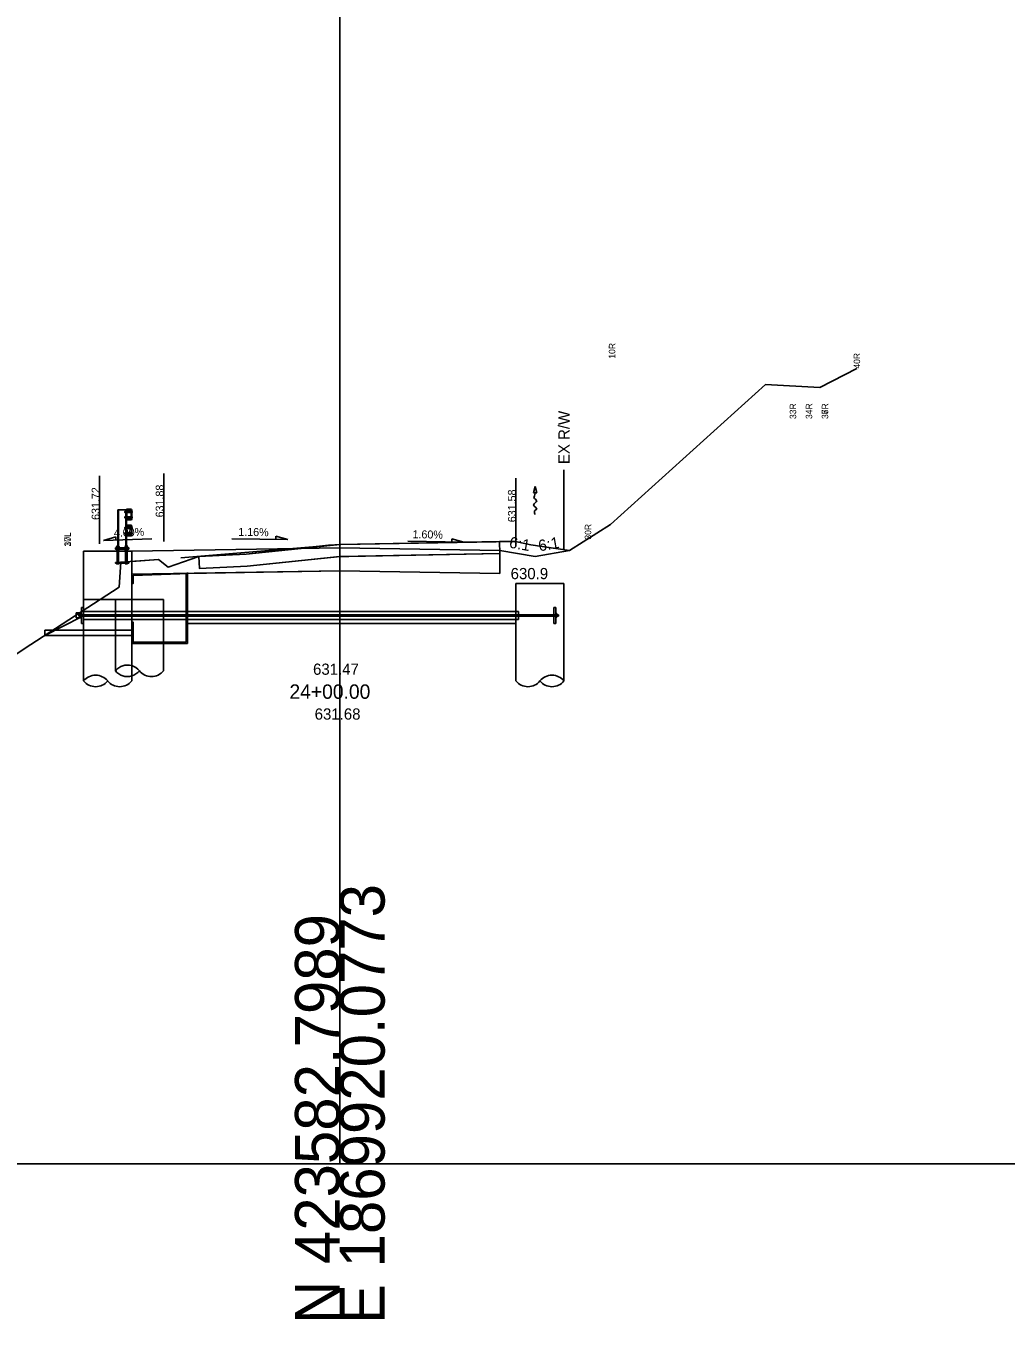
# Model space of a CAD drawing. Extents: x 1866342 to 1870084, y 421982 to 426629.
# Drawn here: x 1866448.5 to 1866509.7, y 424480.9 to 424561.7 of the extents above; entities that cross this region are included whole.
import ezdxf

# ---------------------------------------------------------------- set-up
doc = ezdxf.new("R2010")
doc.units = 0
for name, color, linetype in [('BR_P_Det_Object', 7, 'Continuous'), ('BR_P_Drain_Object', 7, 'Continuous'), ('BR_P_Gen_Hatch', 7, 'Continuous'), ('BR_P_Gen_Porous_Backfill', 7, 'Continuous'), ('BR_P_Sub_Deep_Hidden', 7, 'Continuous'), ('BR_P_Sub_Deep_Object', 7, 'Continuous'), ('BR_P_Sub_Object', 7, 'Continuous'), ('DR_P_Flow_Arrow', 7, 'Continuous'), ('GK_Cells', 7, 'Continuous'), ('RW_X_Fee_RW', 7, 'Continuous'), ('ST_Details', 7, 'Continuous'), ('XS_P_Annotation', 7, 'Continuous'), ('XS_P_Earthwork_Shapes', 7, 'Continuous'), ('XS_P_Finished_Grade', 7, 'Continuous'), ('XS_P_Pavt_Surface', 7, 'Continuous'), ('XS_P_Subgrade', 7, 'Continuous'), ('XS_P_Text_Info', 7, 'Continuous'), ('XS_P_Text_MarkedPoint', 7, 'Continuous'), ('XS_X_Ground_Line', 7, 'Continuous')]:
    doc.layers.add(name, color=color, linetype=linetype)

msp = doc.modelspace()

# ---------------------------------------------------------------- linework, layer by layer
at = {"layer": 'BR_P_Det_Object'}
for p, q in [((1866451.66, 424524.746), (1866451.66, 424525.044)), ((1866451.66, 424525.044), (1866451.994, 424525.044)), ((1866451.994, 424524.746), (1866451.66, 424524.746)), ((1866451.827, 424524.938), (1866481.785, 424524.938)), ((1866451.827, 424524.855), (1866451.827, 424524.938)), ((1866451.827, 424524.855), (1866481.785, 424524.855)), ((1866451.994, 424524.991), (1866451.93, 424524.991)), ((1866451.93, 424524.802), (1866451.93, 424524.991)), ((1866451.994, 424524.802), (1866451.93, 424524.802)), ((1866451.994, 424524.396), (1866451.994, 424525.396)), ((1866451.994, 424525.396), (1866452.119, 424525.396)), ((1866452.119, 424525.396), (1866452.119, 424524.396)), ((1866452.119, 424525.146), (1866455.119, 424525.146)), ((1866481.494, 424525.396), (1866481.494, 424524.396)), ((1866481.619, 424525.396), (1866481.494, 424525.396)), ((1866481.619, 424524.396), (1866481.619, 424525.396)), ((1866481.619, 424525.011), (1866481.682, 424525.011)), ((1866481.619, 424524.781), (1866481.682, 424524.781)), ((1866481.682, 424524.781), (1866481.682, 424525.011)), ((1866481.785, 424524.855), (1866481.785, 424524.938)), ((1866452.119, 424524.396), (1866451.994, 424524.396)), ((1866452.119, 424524.646), (1866455.119, 424524.646)), ((1866481.619, 424524.396), (1866481.494, 424524.396))]:
    msp.add_line(p, q, dxfattribs=at)
at = {"layer": 'BR_P_Drain_Object'}
for p, q in [((1866455.119, 424525.146), (1866479.285, 424525.146)), ((1866479.285, 424525.146), (1866479.285, 424524.646)), ((1866449.695, 424523.98), (1866455.119, 424523.98)), ((1866449.695, 424523.646), (1866449.695, 424523.98)), ((1866455.119, 424524.646), (1866479.285, 424524.646)), ((1866449.695, 424523.646), (1866455.119, 424523.646))]:
    msp.add_line(p, q, dxfattribs=at)
at = {"layer": 'BR_P_Gen_Hatch'}
msp.add_lwpolyline([(1866455.119, 424526.879), (1866455.202, 424526.879), (1866455.202, 424527.379), (1866458.519, 424527.502), (1866458.519, 424523.23), (1866455.202, 424523.23), (1866455.202, 424524.48), (1866455.119, 424524.48)], close=True, dxfattribs=at)
at = {"layer": 'BR_P_Gen_Porous_Backfill'}
for p, q in [((1866455.202, 424527.379), (1866458.119, 424527.496)), ((1866455.202, 424526.879), (1866455.202, 424527.379)), ((1866458.519, 424527.502), (1866458.119, 424527.496)), ((1866458.519, 424523.23), (1866458.519, 424527.502)), ((1866455.202, 424526.879), (1866455.119, 424526.879)), ((1866455.202, 424524.48), (1866455.119, 424524.48)), ((1866455.202, 424523.23), (1866455.202, 424524.48)), ((1866455.202, 424523.23), (1866458.519, 424523.23))]:
    msp.add_line(p, q, dxfattribs=at)
at = {"layer": 'BR_P_Sub_Deep_Hidden'}
msp.add_line((1866457.103, 424525.896), (1866455.119, 424525.896), dxfattribs=at)
for points in [[(1866454.103, 424521.433), (1866454.103, 424525.896)], [(1866457.103, 424523.146), (1866457.103, 424525.896)]]:
    msp.add_lwpolyline(points, dxfattribs=at)
for centre, major_axis, start_param, end_param in [((1866454.853, 424520.83), (0.908, 0.32), 0.952163, 2.125879), ((1866454.853, 424522.036), (0.908, -0.32), 4.157306, 5.331022)]:
    msp.add_ellipse(centre, major_axis=major_axis, ratio=0.999997, start_param=start_param, end_param=end_param, dxfattribs=at)
at = {"layer": 'BR_P_Sub_Deep_Object'}
msp.add_line((1866479.119, 424526.896), (1866482.119, 424526.896), dxfattribs=at)
for points in [[(1866479.119, 424520.8), (1866479.119, 424526.896)], [(1866482.119, 424520.8), (1866482.119, 424526.896)], [(1866452.119, 424520.8), (1866452.119, 424525.896)], [(1866455.119, 424520.8), (1866455.119, 424525.896)], [(1866457.103, 424521.433), (1866457.103, 424523.146)]]:
    msp.add_lwpolyline(points, dxfattribs=at)
for centre, major_axis, start_param, end_param in [((1866454.853, 424520.83), (0.908, 0.32), 0.338571, 0.952163), ((1866452.869, 424520.197), (0.908, 0.32), 0.338571, 2.125879), ((1866452.869, 424521.403), (0.908, -0.32), 4.157306, 5.944615), ((1866454.369, 424521.403), (0.908, 0.32), 3.480163, 5.267472), ((1866454.853, 424522.036), (0.908, -0.32), 5.331022, 5.944615), ((1866456.353, 424522.036), (0.908, 0.32), 3.480163, 5.267472), ((1866479.869, 424521.403), (-0.908, 0.32), 1.015713, 2.803022), ((1866481.369, 424520.197), (-0.908, 0.32), 4.157306, 5.944615), ((1866481.369, 424521.403), (-0.908, -0.32), 0.33857, 2.125879)]:
    msp.add_ellipse(centre, major_axis=major_axis, ratio=0.999997, start_param=start_param, end_param=end_param, dxfattribs=at)
at = {"layer": 'BR_P_Sub_Object'}
for p, q in [((1866455.119, 424528.896), (1866452.119, 424528.896)), ((1866452.119, 424528.896), (1866452.119, 424525.896)), ((1866455.119, 424525.896), (1866455.119, 424528.896))]:
    msp.add_line(p, q, dxfattribs=at)
msp.add_lwpolyline([(1866455.119, 424525.896), (1866452.119, 424525.896)], dxfattribs=at)
at = {"layer": 'DR_P_Flow_Arrow'}
for p, q in [((1866480.205, 424532.54), (1866480.312, 424532.94)), ((1866480.312, 424532.94), (1866480.419, 424532.54)), ((1866480.419, 424532.54), (1866480.205, 424532.54))]:
    msp.add_line(p, q, dxfattribs=at)
msp.add_spline([(1866480.311, 424532.54), (1866480.311, 424532.525), (1866480.273, 424532.36), (1866480.237, 424532.256), (1866480.421, 424532.044), (1866480.215, 424531.801), (1866480.421, 424531.521), (1866480.309, 424531.465), (1866480.312, 424531.19)], degree=3, dxfattribs=at)
at = {"layer": 'GK_Cells'}
for p, q in [((1866468.119, 424490.634), (1866468.119, 424639.643)), ((1866368.119, 424490.634), (1866468.119, 424490.634)), ((1866468.119, 424490.634), (1866568.119, 424490.634))]:
    msp.add_line(p, q, dxfattribs=at)
at = {"layer": 'RW_X_Fee_RW'}
msp.add_line((1866482.119, 424528.993), (1866482.119, 424533.993), dxfattribs=at)
at = {"layer": 'ST_Details'}
for p, q in [((1866454.254, 424531.48), (1866454.254, 424529.261)), ((1866454.785, 424531.48), (1866454.254, 424531.48)), ((1866454.292, 424531.48), (1866454.292, 424529.255)), ((1866454.701, 424531.381), (1866454.685, 424531.381)), ((1866454.685, 424531.381), (1866454.685, 424531.329)), ((1866454.701, 424531.329), (1866454.685, 424531.329)), ((1866454.701, 424531.388), (1866454.701, 424531.321)), ((1866454.71, 424531.333), (1866454.747, 424531.333)), ((1866454.747, 424531.399), (1866454.711, 424531.399)), ((1866454.711, 424531.377), (1866454.747, 424531.377)), ((1866454.711, 424531.31), (1866454.747, 424531.31)), ((1866454.747, 424531.48), (1866454.747, 424529.255)), ((1866454.747, 424531.31), (1866454.747, 424531.399)), ((1866454.785, 424531.48), (1866454.785, 424529.261)), ((1866454.785, 424531.469), (1866454.785, 424530.907)), ((1866454.811, 424531.469), (1866454.811, 424530.907)), ((1866454.811, 424531.381), (1866455.093, 424531.381)), ((1866454.811, 424531.329), (1866455.093, 424531.329)), ((1866455.067, 424531.521), (1866454.837, 424531.521)), ((1866455.067, 424531.495), (1866454.837, 424531.495)), ((1866455.093, 424530.907), (1866455.093, 424531.469)), ((1866455.119, 424530.907), (1866455.119, 424531.469)), ((1866454.701, 424531.047), (1866454.685, 424531.047)), ((1866454.685, 424531.047), (1866454.685, 424530.995)), ((1866454.701, 424530.995), (1866454.685, 424530.995)), ((1866454.701, 424531.055), (1866454.701, 424530.988)), ((1866454.71, 424530.999), (1866454.747, 424530.999)), ((1866454.747, 424531.066), (1866454.711, 424531.066)), ((1866454.711, 424531.043), (1866454.747, 424531.043)), ((1866454.711, 424530.977), (1866454.747, 424530.977)), ((1866454.747, 424530.399), (1866454.711, 424530.399)), ((1866454.747, 424530.977), (1866454.747, 424531.066)), ((1866454.747, 424530.31), (1866454.747, 424530.399)), ((1866454.785, 424530.49), (1866454.785, 424529.886)), ((1866454.811, 424531.047), (1866455.093, 424531.047)), ((1866454.811, 424530.995), (1866455.093, 424530.995)), ((1866454.811, 424530.469), (1866454.811, 424529.907)), ((1866455.087, 424530.521), (1866454.817, 424530.521)), ((1866454.837, 424530.881), (1866455.067, 424530.881)), ((1866454.837, 424530.855), (1866455.067, 424530.855)), ((1866455.067, 424530.495), (1866454.837, 424530.495)), ((1866455.093, 424529.907), (1866455.093, 424530.469)), ((1866455.119, 424529.886), (1866455.119, 424530.49)), ((1866454.701, 424530.381), (1866454.685, 424530.381)), ((1866454.685, 424530.381), (1866454.685, 424530.329)), ((1866454.701, 424530.329), (1866454.685, 424530.329)), ((1866454.701, 424530.047), (1866454.685, 424530.047)), ((1866454.685, 424530.047), (1866454.685, 424529.995)), ((1866454.701, 424529.995), (1866454.685, 424529.995)), ((1866454.701, 424530.388), (1866454.701, 424530.321)), ((1866454.701, 424530.055), (1866454.701, 424529.988)), ((1866454.71, 424530.333), (1866454.747, 424530.333)), ((1866454.71, 424529.999), (1866454.747, 424529.999)), ((1866454.711, 424530.377), (1866454.747, 424530.377)), ((1866454.711, 424530.31), (1866454.747, 424530.31)), ((1866454.747, 424530.066), (1866454.711, 424530.066)), ((1866454.711, 424530.043), (1866454.747, 424530.043)), ((1866454.711, 424529.977), (1866454.747, 424529.977)), ((1866454.747, 424529.977), (1866454.747, 424530.066)), ((1866454.811, 424530.381), (1866455.093, 424530.381)), ((1866454.811, 424530.329), (1866455.093, 424530.329)), ((1866454.811, 424530.047), (1866455.093, 424530.047)), ((1866454.811, 424529.995), (1866455.093, 424529.995)), ((1866454.817, 424529.855), (1866455.087, 424529.855)), ((1866454.837, 424529.881), (1866455.067, 424529.881)), ((1866454.171, 424529.13), (1866454.337, 424529.13)), ((1866454.171, 424529.115), (1866454.171, 424529.13)), ((1866454.337, 424529.115), (1866454.171, 424529.115)), ((1866454.171, 424529.032), (1866454.337, 424529.032)), ((1866454.171, 424529.017), (1866454.171, 424529.032)), ((1866454.337, 424529.017), (1866454.171, 424529.017)), ((1866454.176, 424529.196), (1866454.176, 424529.13)), ((1866454.332, 424529.13), (1866454.176, 424529.13)), ((1866454.176, 424528.987), (1866454.176, 424529.017)), ((1866454.195, 424529.212), (1866454.312, 424529.212)), ((1866454.195, 424528.972), (1866454.312, 424528.972)), ((1866454.212, 424529.251), (1866454.223, 424529.261)), ((1866454.212, 424529.251), (1866454.296, 424529.251)), ((1866454.212, 424529.251), (1866454.212, 424529.212)), ((1866454.212, 424529.24), (1866454.296, 424529.24)), ((1866454.212, 424529.23), (1866454.296, 424529.23)), ((1866454.212, 424529.22), (1866454.296, 424529.22)), ((1866454.212, 424529.115), (1866454.212, 424529.032)), ((1866454.212, 424528.907), (1866454.212, 424528.972)), ((1866454.212, 424528.907), (1866454.212, 424528.188)), ((1866454.215, 424529.196), (1866454.215, 424529.13)), ((1866454.215, 424528.987), (1866454.215, 424529.017)), ((1866454.285, 424529.261), (1866454.223, 424529.261)), ((1866454.285, 424529.261), (1866454.296, 424529.251)), ((1866454.293, 424529.196), (1866454.293, 424529.13)), ((1866454.293, 424528.987), (1866454.293, 424529.017)), ((1866454.296, 424529.212), (1866454.296, 424529.251)), ((1866454.296, 424529.032), (1866454.296, 424529.115)), ((1866454.296, 424528.907), (1866454.296, 424528.972)), ((1866454.296, 424528.188), (1866454.296, 424528.907)), ((1866454.332, 424529.196), (1866454.332, 424529.13)), ((1866454.332, 424528.987), (1866454.332, 424529.017)), ((1866454.337, 424529.13), (1866454.337, 424529.115)), ((1866454.337, 424529.032), (1866454.337, 424529.017)), ((1866454.868, 424529.13), (1866454.702, 424529.13)), ((1866454.702, 424529.13), (1866454.702, 424529.115)), ((1866454.702, 424529.115), (1866454.868, 424529.115)), ((1866454.702, 424529.032), (1866454.868, 424529.032)), ((1866454.702, 424529.017), (1866454.702, 424529.032)), ((1866454.868, 424529.017), (1866454.702, 424529.017)), ((1866454.707, 424529.196), (1866454.707, 424529.13)), ((1866454.707, 424529.13), (1866454.863, 424529.13)), ((1866454.707, 424528.987), (1866454.707, 424529.017)), ((1866454.844, 424529.212), (1866454.726, 424529.212)), ((1866454.726, 424528.972), (1866454.844, 424528.972)), ((1866454.754, 424529.261), (1866454.743, 424529.251)), ((1866454.827, 424529.251), (1866454.743, 424529.251)), ((1866454.743, 424529.212), (1866454.743, 424529.251)), ((1866454.827, 424529.24), (1866454.743, 424529.24)), ((1866454.827, 424529.23), (1866454.743, 424529.23)), ((1866454.827, 424529.22), (1866454.743, 424529.22)), ((1866454.743, 424529.032), (1866454.743, 424529.115)), ((1866454.743, 424528.907), (1866454.743, 424528.972)), ((1866454.743, 424528.188), (1866454.743, 424528.907)), ((1866454.746, 424529.196), (1866454.746, 424529.13)), ((1866454.746, 424528.987), (1866454.746, 424529.017)), ((1866454.754, 424529.261), (1866454.816, 424529.261)), ((1866454.827, 424529.251), (1866454.816, 424529.261)), ((1866454.824, 424529.196), (1866454.824, 424529.13)), ((1866454.824, 424528.987), (1866454.824, 424529.017)), ((1866454.827, 424529.251), (1866454.827, 424529.212)), ((1866454.827, 424529.115), (1866454.827, 424529.032)), ((1866454.827, 424528.907), (1866454.827, 424528.972)), ((1866454.827, 424528.907), (1866454.827, 424528.188)), ((1866454.863, 424529.196), (1866454.863, 424529.13)), ((1866454.863, 424528.987), (1866454.863, 424529.017)), ((1866454.868, 424529.115), (1866454.868, 424529.13)), ((1866454.868, 424529.032), (1866454.868, 424529.017)), ((1866454.176, 424528.122), (1866454.176, 424528.157)), ((1866454.195, 424528.106), (1866454.312, 424528.106)), ((1866454.215, 424528.122), (1866454.215, 424528.157)), ((1866454.293, 424528.122), (1866454.293, 424528.157)), ((1866454.332, 424528.122), (1866454.332, 424528.157)), ((1866454.707, 424528.122), (1866454.707, 424528.157)), ((1866454.844, 424528.106), (1866454.726, 424528.106)), ((1866454.746, 424528.122), (1866454.746, 424528.157)), ((1866454.824, 424528.122), (1866454.824, 424528.157)), ((1866454.863, 424528.122), (1866454.863, 424528.157))]:
    msp.add_line(p, q, dxfattribs=at)
for points in [[(1866454.103, 424529.115), (1866454.936, 424529.115), (1866454.936, 424529.032), (1866454.103, 424529.032)], [(1866454.103, 424528.188), (1866454.936, 424528.188), (1866454.936, 424528.157), (1866454.103, 424528.157)]]:
    msp.add_lwpolyline(points, close=True, dxfattribs=at)
for centre, radius, start, end in [((1866454.837, 424531.469), 0.0521, 90, 180), ((1866454.837, 424531.469), 0.026, 90, 180), ((1866455.067, 424531.469), 0.0521, 0, 90), ((1866455.067, 424531.469), 0.026, 0, 90), ((1866455.091, 424531.355), 0.0558, 300, 60), ((1866454.837, 424530.907), 0.0521, 180, 270), ((1866454.817, 424530.49), 0.0312, 90, 180), ((1866454.837, 424530.907), 0.026, 180, 270), ((1866454.837, 424530.469), 0.026, 90, 180), ((1866455.067, 424530.907), 0.0521, 270, 0), ((1866455.067, 424530.907), 0.026, 270, 0), ((1866455.067, 424530.469), 0.026, 0, 90), ((1866455.087, 424530.49), 0.0312, 0, 90), ((1866455.091, 424531.021), 0.0558, 300, 60), ((1866455.091, 424530.355), 0.0558, 300, 60), ((1866454.817, 424529.886), 0.0312, 180, 270), ((1866454.837, 424529.907), 0.026, 180, 270), ((1866455.067, 424529.907), 0.026, 270, 0), ((1866455.087, 424529.886), 0.0312, 270, 0), ((1866455.091, 424530.021), 0.0558, 300, 60)]:
    msp.add_arc(centre, radius, start, end, dxfattribs=at)
for centre, major_axis, ratio, start_param, end_param in [((1866454.711, 424531.388), (0, -0.0111), 0.939759, 3.141593, 6.283185), ((1866454.711, 424531.355), (0, -0.0222), 0.469173, 3.141593, 6.283185), ((1866454.711, 424531.321), (0, 0.0111), 0.939759, 0, 3.141593), ((1866454.711, 424531.055), (0, -0.0111), 0.939759, 3.141593, 6.283185), ((1866454.711, 424531.021), (0, -0.0222), 0.469173, 3.141593, 6.283185), ((1866454.711, 424530.988), (0, 0.0111), 0.939759, 0, 3.141593), ((1866454.711, 424530.388), (0, -0.0111), 0.939759, 3.141593, 6.283185), ((1866454.711, 424530.355), (0, -0.0222), 0.469173, 3.141593, 6.283185), ((1866454.711, 424530.321), (0, 0.0111), 0.939759, 0, 3.141593), ((1866454.711, 424530.055), (0, -0.0111), 0.939759, 3.141593, 6.283185), ((1866454.711, 424530.021), (0, -0.0222), 0.469173, 3.141593, 6.283185), ((1866454.711, 424529.988), (0, 0.0111), 0.939759, 0, 3.141593), ((1866454.195, 424529.196), (0.0195, 0), 0.798056, 0, 3.141593), ((1866454.195, 424528.987), (0.0195, 0), 0.798056, 3.141593, 6.283185), ((1866454.254, 424529.196), (0.0391, 0), 0.399304, 0, 3.141593), ((1866454.254, 424528.987), (0.0391, 0), 0.399304, 3.141593, 6.283185), ((1866454.312, 424529.196), (0.0195, 0), 0.798056, 0, 3.141593), ((1866454.312, 424528.987), (0.0195, 0), 0.798056, 3.141593, 6.283185), ((1866454.726, 424529.196), (-0.0195, 0), 0.798056, 3.141593, 6.283185), ((1866454.726, 424528.987), (0.0195, 0), 0.798056, 3.141593, 6.283185), ((1866454.785, 424529.196), (-0.0391, 0), 0.399304, 3.141593, 6.283185), ((1866454.785, 424528.987), (0.0391, 0), 0.399304, 3.141593, 6.283185), ((1866454.844, 424529.196), (-0.0195, 0), 0.798056, 3.141593, 6.283185), ((1866454.844, 424528.987), (0.0195, 0), 0.798056, 3.141593, 6.283185), ((1866454.195, 424528.122), (0.0195, 0), 0.798056, 3.141593, 6.283185), ((1866454.254, 424528.122), (0.0391, 0), 0.399304, 3.141593, 6.283185), ((1866454.312, 424528.122), (0.0195, 0), 0.798056, 3.141593, 6.283185), ((1866454.726, 424528.122), (-0.0195, 0), 0.798056, 0, 3.141593), ((1866454.785, 424528.122), (-0.0391, 0), 0.399304, 0, 3.141593), ((1866454.844, 424528.122), (-0.0195, 0), 0.798056, 0, 3.141593)]:
    msp.add_ellipse(centre, major_axis=major_axis, ratio=ratio, start_param=start_param, end_param=end_param, dxfattribs=at)
at = {"layer": 'XS_P_Annotation'}
for q in [(1866455.119, 424528.896), (1866478.119, 424528.944)]:
    msp.add_line((1866468.119, 424529.104), q, dxfattribs=at)
at = {"layer": 'XS_P_Earthwork_Shapes'}
for p, q in [((1866480.312, 424528.579), (1866482.473, 424528.939)), ((1866455.119, 424528.27), (1866455.119, 424527.459)), ((1866478.119, 424527.507), (1866478.119, 424528.752)), ((1866468.119, 424527.667), (1866478.119, 424527.507))]:
    msp.add_line(p, q, dxfattribs=at)
for points in [[(1866482.473, 424528.939), (1866480.051, 424529.307), (1866479.099, 424529.518), (1866478.084, 424529.5), (1866478.119, 424528.752), (1866468.691, 424528.58), (1866468.119, 424528.566), (1866462.336, 424527.972), (1866459.36, 424527.815), (1866459.32, 424528.562), (1866457.406, 424527.907), (1866456.797, 424528.375), (1866455.119, 424528.27)], [(1866459.32, 424528.562), (1866462.278, 424528.718), (1866468.119, 424529.318), (1866478.084, 424529.5)], [(1866478.119, 424528.752), (1866478.119, 424528.944), (1866480.312, 424528.579)], [(1866459.36, 424527.815), (1866462.336, 424527.972), (1866468.164, 424528.57), (1866478.098, 424528.752)], [(1866455.119, 424527.459), (1866458.603, 424527.515), (1866468.119, 424527.667)]]:
    msp.add_lwpolyline(points, dxfattribs=at)
at = {"layer": 'XS_P_Finished_Grade'}
for p, q in [((1866478.119, 424528.944), (1866480.312, 424528.579)), ((1866482.473, 424528.939), (1866480.312, 424528.579)), ((1866449.695, 424523.646), (1866451.994, 424524.796))]:
    msp.add_line(p, q, dxfattribs=at)
at = {"layer": 'XS_P_Pavt_Surface'}
for p, q in [((1866458.189, 424528.491), (1866468.189, 424529.322)), ((1866468.189, 424529.322), (1866479.099, 424529.518))]:
    msp.add_line(p, q, dxfattribs=at)
at = {"layer": 'XS_P_Subgrade'}
for p, q in [((1866455.119, 424528.896), (1866455.119, 424527.459)), ((1866455.119, 424528.896), (1866455.119, 424527.459)), ((1866478.119, 424528.944), (1866478.119, 424527.507)), ((1866468.119, 424527.667), (1866455.119, 424527.459)), ((1866458.603, 424523.146), (1866458.603, 424527.579)), ((1866468.119, 424527.667), (1866478.119, 424527.507)), ((1866458.603, 424524.396), (1866479.119, 424524.396)), ((1866455.119, 424523.146), (1866458.603, 424523.146))]:
    msp.add_line(p, q, dxfattribs=at)
at = {"layer": 'XS_P_Text_Info'}
for p, q in [((1866457.119, 424529.515), (1866457.119, 424533.765)), ((1866453.119, 424529.355), (1866453.119, 424533.605)), ((1866479.119, 424529.212), (1866479.119, 424533.462)), ((1866454.119, 424529.795), (1866453.369, 424529.565)), ((1866456.369, 424529.685), (1866453.369, 424529.565)), ((1866454.119, 424529.595), (1866454.119, 424529.795)), ((1866461.369, 424529.666), (1866464.869, 424529.625)), ((1866464.119, 424529.834), (1866464.869, 424529.625)), ((1866464.119, 424529.634), (1866464.119, 424529.834)), ((1866475.119, 424529.676), (1866475.869, 424529.464)), ((1866475.119, 424529.476), (1866475.119, 424529.676)), ((1866472.369, 424529.52), (1866475.869, 424529.464))]:
    msp.add_line(p, q, dxfattribs=at)
at = {"layer": 'XS_X_Ground_Line'}
msp.add_line((1866452.119, 424528.896), (1866452.119, 424526.896), dxfattribs=at)
msp.add_lwpolyline([(1866392.137, 424491.219), (1866392.538, 424491.21), (1866393.969, 424491.18), (1866395.459, 424491.148), (1866429.878, 424511.061), (1866443.367, 424519.61), (1866447.507, 424522.212), (1866448.409, 424522.81), (1866454.337, 424526.665), (1866454.438, 424528.228), (1866456.797, 424528.375), (1866457.406, 424527.907), (1866459.32, 424528.562), (1866462.278, 424528.718), (1866467.401, 424529.272), (1866468.189, 424529.322), (1866479.099, 424529.518), (1866480.051, 424529.307), (1866482.473, 424528.939), (1866485.029, 424530.574), (1866494.709, 424539.323), (1866498.09, 424539.124), (1866500.413, 424540.304)], dxfattribs=at)

# ---------------------------------------------------------------- texts
at = {"layer": 'GK_Cells'}
for s, p in [('E 1869920.0773', (1866470.919, 424480.634)), ('N 423582.7989', (1866468.119, 424480.634))]:
    msp.add_text(s, height=2.8, rotation=90, dxfattribs=at).set_placement(p)
at = {"layer": 'RW_X_Fee_RW'}
msp.add_text('EX R/W', height=0.7, rotation=90, dxfattribs=at).set_placement((1866482.469, 424534.343))
at = {"layer": 'XS_P_Annotation'}
for rotation, p in [(349.95478, (1866478.659, 424529.133)), (10.04522, (1866480.586, 424528.889))]:
    msp.add_text('6:1', height=0.7, rotation=rotation, dxfattribs=at).set_placement(p)
for s, height, p in [('630.9', 0.7, (1866478.786, 424527.155)), ('631.47', 0.7, (1866466.446, 424521.184)), ('24+00.00', 0.9, (1866464.972, 424519.684)), ('631.68', 0.7, (1866466.548, 424518.384))]:
    msp.add_text(s, height=height, dxfattribs=at).set_placement(p)
at = {"layer": 'XS_P_Text_Info'}
for s, rotation, p in [('631.72', 90, (1866453.119, 424530.855)), ('631.88', 90, (1866457.119, 424531.015)), ('631.58', 90, (1866479.119, 424530.712)), ('4.00%', 2.29061, (1866454.013, 424529.792)), ('1.16%', 359.33362, (1866461.775, 424529.861)), ('1.60%', 359.08335, (1866472.655, 424529.715))]:
    msp.add_text(s, height=0.5, rotation=rotation, dxfattribs=at).set_placement(p)
at = {"layer": 'XS_P_Text_MarkedPoint'}
for s, p in [('10R', (1866485.319, 424540.925)), ('40R', (1866500.613, 424540.304)), ('33R', (1866496.62, 424537.158)), ('34R', (1866497.62, 424537.158)), ('35R', (1866498.62, 424537.158)), ('36R', (1866498.62, 424537.158)), ('37R', (1866498.62, 424537.158)), ('30R', (1866483.819, 424529.625)), ('10L', (1866451.319, 424529.195)), ('37L', (1866451.319, 424529.195))]:
    msp.add_text(s, height=0.4, rotation=90, dxfattribs=at).set_placement(p)

doc.saveas('drawing.dxf')
